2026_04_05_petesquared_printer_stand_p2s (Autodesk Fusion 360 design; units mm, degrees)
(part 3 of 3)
sketch "poop_bin" plane through (203.2508, 0, 0) normal (1, 0, 0) x axis (0, 1, 0)
  line L1 (473.3614, -12.446) -> (87.884, -12.446)
  line L2 (477.012, -33.1964) -> (477.012, -0.508)
  line L3 (87.884, -53.086) -> (481.584, -37.592)
  line L4 (87.884, -12.446) -> (87.884, -53.086)
  line L5 (481.584, -5.08) -> (481.584, -37.592)
  line L6 (92.456, -48.3305) -> (92.456, -12.446)
  line L7 (477.012, -33.1964) -> (92.456, -48.3305)
  line L8 (477.012, -37.7719) -> (477.012, -33.1964)
  line L9 (473.3614, -12.446) -> (473.3614, -33.3401)
  line L10 (138.684, -18.9484) -> (138.684, -12.446)
  line L11 (164.084, -18.9484) -> (138.684, -18.9484)
  line L12 (164.084, -12.446) -> (164.084, -18.9484)
  line L13 (367.284, -18.9484) -> (367.284, -12.446)
  line L14 (392.684, -18.9484) -> (367.284, -18.9484)
  line L15 (392.684, -12.446) -> (392.684, -18.9484)
  line L16 (477.012, -12.446) -> (473.3614, -12.446)
  line L17 (283.4191, -11.9284) -> (284.734, -45.339)
  line L18 (68.8487, -53.8351) -> (87.884, -53.086)
  line L19 (68.8487, -49.0797) -> (68.8487, -53.8351)
  line L20 (87.884, -48.3305) -> (68.8487, -49.0797)
  arc A1 centre (477.012, -5.08) radius 4.572 clockwise from (477.012, -0.508) to (481.584, -5.08)
  point P3 (477.012, -0.508)
  point P7 (477.012, -12.192)
  point P12 (92.456, -12.446)
  point P2 (481.584, -37.592)
  point P9 (481.584, -37.592)
  point P17 (477.012, -37.7719)
  point P18 (473.3614, -33.3401)
  point P20 (138.684, -12.446)
  point P23 (164.084, -12.446)
  point P24 (367.284, -12.446)
  point P27 (392.684, -12.446)
  point P22 (164.084, -18.9484)
  point P25 (367.284, -18.9484)
  point P6 (473.3614, -12.446)
  point P19 (473.3614, -12.446)
  point P16 (477.012, -5.08)
  point P10 (477.012, -0.508)
  point P28 (477.012, -12.446)
  point P29 (284.734, -45.339)
  point P33 (87.884, -48.3305)
  point P13 (92.456, -48.3305)
  point P4 (87.884, -53.086)
  point P5 (87.884, -12.446)
  point P11 (477.012, 0)
  point P15 (481.584, -5.08)
  point P21 (138.684, -18.9484)
  point P32 (68.8487, -49.0797)
  horizontal L1
  vertical L2
  vertical L4
  vertical P3 P7
  parallel L2 L5
  coincident L1 P12
  perpendicular L1 L6
  parallel L3 L7
  tangent L5 A1
  coincident P2 P9
  coincident L3 P17
  parallel L2 L8
  coincident L7 P18
  vertical L9
  coincident L1 P20
  perpendicular L1 L10
  perpendicular L10 L11
  coincident L1 P23
  perpendicular L1 L12
  coincident L1 P24
  perpendicular L1 L13
  perpendicular L13 L14
  coincident L1 P27
  perpendicular L1 L15
  horizontal P22 P25
  equal L11 L14
  coincident P6 P19
  vertical P7 P16
  coincident P3 P10
  coincident L2 P28
  perpendicular L2 L16
  midpoint L3 P29
  perpendicular L3 L17
  coincident L4 P33
  horizontal P13 P33
  collinear L3 L18
  parallel L18 L20
  vertical L19
  dimension "d3058" distance P4 P5 = 40.64
  dimension "d3064" distance P6 P7 = 0.254
  dimension "d3100" distance L3 L7 = 4.572
  dimension "d3101" distance L4 L6 = 4.572 (= "d3100")
  dimension "d3104" distance P10 P11 = 0.508
  dimension "d3105" distance P15 P16 = 4.572
  dimension "d3106" distance P2 P7 = 25.4
  dimension "d3114" distance L2 L9 = 3.6506
  dimension "d3155" distance P21 P22 = 25.4
  dimension "d3156" distance P5 P20 = 50.8
  dimension "d3157" distance P20 P21 = 6.5024
  dimension "d3158" distance P22 P25 = 203.2
  dimension "d3323" distance P2 P4 = 393.7
  dimension "d3325" distance P32 P33 = 19.05
sketch "poop_chute" plane through (0, 0, 0) normal (0, 0, 1) x axis (-1, 0, 0)
  line L1 (214.249, 0) -> (214.249, -477.012)
  line L2 (-214.249, 0) -> (214.249, 0)
  line L3 (-214.249, -477.012) -> (-214.249, 0)
  line L4 (-127, -477.012) -> (-214.249, -477.012)
  line L5 (-127, -417.9654) -> (-127, -477.012)
  line L6 (-113.5296, -404.495) -> (-127, -417.9654)
  line L7 (113.5296, -404.495) -> (-113.5296, -404.495)
  line L8 (127, -417.9654) -> (113.5296, -404.495)
  line L9 (127, -477.012) -> (127, -417.9654)
  line L10 (214.249, -477.012) -> (127, -477.012)
  line L11 (0, -481.584) -> (127, -481.584)
  line L12 (115.4234, -399.923) -> (0, -399.923)
  line L13 (131.572, -477.012) -> (131.572, -416.0716)
  line L14 (150.622, -421.1516) -> (150.622, -471.932)
  line L15 (131.572, -416.0716) -> (145.542, -416.0716)
  line L16 (0, -399.923) -> (0, -481.584)
  line L17 (0, -477.012) -> (0, -481.584)
  line L18 (127, -417.9654) -> (127, -477.012)
  line L19 (113.5296, -404.495) -> (127, -417.9654)
  line L20 (0, -404.495) -> (113.5296, -404.495)
  line L21 (127, -477.012) -> (0, -477.012)
  line L22 (0, -399.923) -> (0, -404.495)
  line L23 (131.572, -416.0716) -> (115.4234, -399.923)
  line L24 (145.542, -477.012) -> (131.572, -477.012)
  line L25 (95.25, -404.495) -> (95.25, -477.012)
  line L26 (95.25, -481.584) -> (95.25, -477.012)
  line L27 (95.25, -399.923) -> (95.25, -404.495)
  line L28 (90.678, -404.495) -> (90.678, -477.012)
  circle C1 centre (141.732, -428.7716) radius 1.905
  circle C2 centre (141.732, -464.312) radius 1.905
  arc A1 centre (145.542, -421.1516) radius 5.08 clockwise from (145.542, -416.0716) to (150.622, -421.1516)
  arc A2 centre (145.542, -471.932) radius 5.08 clockwise from (150.622, -471.932) to (145.542, -477.012)
  arc A3 centre (127, -477.012) radius 4.572 clockwise from (131.572, -477.012) to (127, -481.584)
  circle C3 centre (-171.196, -30.099) radius 1.6002
  circle C4 centre (-171.196, -372.491) radius 1.6002
  circle C5 centre (171.196, -30.099) radius 1.6002
  circle C6 centre (171.196, -372.491) radius 1.6002
  circle C7 centre (-197.1548, -68.326) radius 1.6002
  circle C8 centre (197.1548, -423.926) radius 1.6002
  circle C9 centre (197.1548, -68.326) radius 1.6002
  circle C10 centre (-197.1548, -423.926) radius 1.6002
  circle C11 centre (-152.4, -13.716) radius 1.6002
  circle C12 centre (197.1548, -246.126) radius 1.6002
  circle C13 centre (152.4, -13.716) radius 1.6002
  circle C14 centre (-197.1548, -246.126) radius 1.6002
  circle C15 centre (0, -13.716) radius 1.6002
  point P24 (0, -399.923)
  point P25 (0, 0)
  point P26 (0, -477.012)
  point P27 (127, -417.9654)
  point P29 (0, -404.495)
  point P31 (131.572, -416.0716)
  point P20 (127, -477.012)
  point P32 (127, -477.012)
  point P33 (131.572, -477.012)
  point P34 (141.732, -416.0716)
  point P35 (141.732, -428.7716)
  point P36 (141.732, -464.312)
  point P22 (150.622, -416.0716)
  point P58 (95.25, -477.012)
  point P59 (95.25, -404.495)
  point P60 (95.25, -481.584)
  point P61 (95.25, -399.923)
  point P62 (90.678, -477.012)
  point P63 (90.678, -404.495)
  point P44 (127, -477.012)
  horizontal L11
  horizontal L12
  vertical L13
  perpendicular L12 L14
  perpendicular L13 L15
  vertical P24 P25
  coincident L16 P26
  perpendicular L11 L17
  coincident L9 P27
  midpoint L7 P29
  horizontal L20
  perpendicular L16 L21
  vertical L18
  equal L17 L22
  collinear L8 L19
  coincident L13 P31
  parallel L19 L23
  coincident P20 P32
  horizontal L24
  horizontal P32 P33
  vertical P34 P35
  vertical P34 P36
  coincident L15 P34
  coincident P22 L15
  coincident P22 L14
  tangent L15 A1
  tangent L14 A1
  tangent L14 A2
  tangent L24 A2
  equal A1 A2
  tangent L11 A3
  tangent L13 A3
  coincident L21 P58
  coincident L20 P59
  vertical L25
  coincident L11 P60
  perpendicular L11 L26
  coincident L12 P61
  perpendicular L12 L27
  coincident L21 P62
  coincident L20 P63
  vertical L28
  dimension "d3066" angle L19 L20 = 135
  dimension "d3067" distance L12 L20 = 4.572
  dimension "d3068" distance P20 L13 = 4.572 (= "d3067")
  dimension "d3071" distance L19 L23 = 4.572 (= "d3067")
  dimension "d3080" distance P22 P31 = 19.05
  dimension "d3081" diameter C1 = 3.81 (= "hole_screw_3dprint")
  dimension "d3082" distance P34 P35 = 12.7 (= "hole_screw_brace_offset / 2")
  dimension "d3083" diameter C2 = 3.81 (= "hole_screw_3dprint")
  dimension "d3084" distance L24 P36 = 12.7 (= "hole_screw_brace_offset / 2")
  dimension "d3085" radius A1 = 5.08
  dimension "d3086" distance P31 P34 = 10.16
  dimension "d3662" distance P44 P58 = 31.75
  dimension "d3663" distance P60 P62 = 4.572 (= "d3067")
extrude "Extrude1" new body sketch "poop_chute" profile of L7 L11 L12 L17 L20 L21 L22 L25 L26 L27 L28 along normal blind 203.2 bodies "poop_chute"
draft "Draft1" Angle1 45 Angle2 0
extrude "Extrude2" add sketch "poop_chute" profile of L7 L8 L9 L11 L12 L13 L14 L15 L18 L19 L20 L21 L23 L24 C1 C2 A1 A2 A3 L25 L26 L27 along normal blind 6.35
chamfer "Chamfer1" distance 3.81
mirror "Mirror1" mirrorStitchTolerance 0.1016
fillet "Fillet1" radius 1.524
sketch "base_bracket_feet" plane through (0, 0, -83.312) normal (0, 0, -1) x axis (1, 0, 0)
  line L1 (-103.0086, -418.3296) -> (-81.28, -483.616)
  line L2 (-138.9296, -382.4086) -> (-103.0086, -418.3296)
  line L3 (-204.216, -360.68) -> (-138.9296, -382.4086)
  line L4 (-220.98, -360.68) -> (-204.216, -360.68)
  line L5 (-220.98, -500.38) -> (-220.98, -360.68)
  line L6 (-81.28, -500.38) -> (-220.98, -500.38)
  line L7 (-81.28, -483.616) -> (-81.28, -500.38)
  line L8 (-220.98, -500.38) -> (-144.78, -500.38)
  line L9 (-220.98, -424.18) -> (-220.98, -500.38)
  line L10 (-144.78, -473.4392) -> (-144.78, -500.38)
  line L11 (-194.0392, -424.18) -> (-220.98, -424.18)
  line L12 (-194.0392, -424.18) -> (-144.78, -473.4392)
  line L13 (-220.98, -102.362) -> (-220.98, -26.162)
  line L14 (-194.0392, -102.362) -> (-220.98, -102.362)
  line L15 (-144.78, -26.162) -> (-144.78, -53.1028)
  line L16 (-220.98, -26.162) -> (-144.78, -26.162)
  line L17 (-144.78, -53.1028) -> (-194.0392, -102.362)
  line L18 (-182.88, -26.162) -> (-182.88, -64.262)
  line L19 (-220.98, -64.262) -> (-182.88, -64.262)
  line L20 (-220.98, -462.28) -> (-182.88, -462.28)
  line L21 (-182.88, -500.38) -> (-182.88, -462.28)
  line L22 (0, -20) -> (0, -2.5)
  circle C1 centre (-152.4, -431.8) radius 8.128
  circle C2 centre (-152.4, -76.2) radius 5.207
  circle C3 centre (-182.88, -462.28) radius 6.096
  circle C4 centre (-182.88, -64.262) radius 6.096
  circle C5 centre (182.88, -462.28) radius 6.096
  circle C6 centre (182.88, -64.262) radius 6.096
  point P13 (-220.98, -424.18)
  point P15 (-220.98, -424.18)
  point P10 (-220.98, -500.38)
  point P17 (-220.98, -500.38)
  point P19 (-220.98, -102.362)
  point P26 (-182.88, -64.262)
  point P27 (-182.88, -64.262)
  point P28 (-182.88, -26.162)
  point P29 (-182.88, -64.262)
  point P30 (-220.98, -64.262)
  point P32 (-220.98, -462.28)
  point P25 (-182.88, -462.28)
  point P33 (-182.88, -462.28)
  point P34 (-182.88, -500.38)
  point P31 (-182.88, -462.28)
  point P12 (-144.78, -500.38)
  point P18 (-220.98, -26.162)
  point P23 (-216.408, -30.734)
  horizontal L8
  perpendicular L8 L9
  equal L8 L9
  perpendicular L8 L10
  perpendicular L9 L11
  equal L10 L11
  coincident P13 P15
  coincident P10 P17
  vertical L13
  perpendicular L13 L14
  horizontal L16
  vertical P13 P19
  equal L11 L14
  equal L9 L13
  vertical L15
  equal L14 L15
  coincident P26 P27
  coincident L16 P28
  perpendicular L16 L18
  coincident P26 P29
  coincident L13 P30
  perpendicular L13 L19
  equal L18 L19
  coincident L9 P32
  coincident P25 P33
  coincident L8 P34
  horizontal L20
  vertical L21
  equal L20 L21
  equal L19 L20
  coincident P25 P31
  symmetric C3 L22 C5
  symmetric C4 L22 C6
  dimension "d3508" distance P10 P12 = 76.2
  dimension "d3523" distance P18 P23 = 4.572 (= "dado_material_depth")
  dimension "d3587" diameter C3 = 12.192 (= "hole_threaded_inserts")
  dimension "d3588" distance P17 P25 = 38.1
  dimension "d3590" distance L12 P25 = 19.05
  dimension "d3592" angle L14 L17 = 135
  dimension "d3594" diameter C4 = 12.192 (= "hole_threaded_inserts")
extrude "Extrude34" new body sketch "base_bracket_feet" profile of L5 L6 L8 L9 L10 L11 L12 L13 L14 L15 L16 C3 L17 C4 along normal blind 12.192 (= "material_thickness") bodies "base_bracket_foot_back_left", "base_bracket_foot_front_left"
mirror "Mirror8" mirrorStitchTolerance 0.1016 bodies "base_bracket_foot_back_right", "base_bracket_foot_front_right"
fillet "Fillet3" radius 5.969
extrude "Extrude6" new body sketch "poop_bin" profile of L1 L10 L11 L12 L13 L14 L15 blind -6.35 from offset -18.796 (= "-material_thickness - 0.26 in")
extrude "Extrude7" sketch "poop_bin" profile of L1 L2 L3 L4 L6 L7 L8 L9 L10 L11 L12 L13 L14 L15 L16 blind -4.572 (= "-wall_thickness_3d_printed")
extrude "Extrude8" sketch "poop_bin" profile of L1 L2 L3 L4 L6 L7 L8 L9 L16 to an object
extrude "Extrude18" sketch "poop_bin" profile of L4 L18 L19 L20 blind 50.8
extrude "Extrude9" add sketch "poop_bin" profile of L2 L3 L5 A1 L8 to an object from offset -62.23
work_plane "WorkPlane2" RotateAngle 90
split "Split2"
mirror "Mirror7" mirrorStitchTolerance 0.1016
step "SurfaceRuled2" ruledDistance 5.08 ruledAngle 0
rectangular_pattern "R-Pattern2" uSpaceDistance -152.4 vSpaceDistance 0
split_face "SplitFace24"
step "SurfaceRuled3" ruledDistance 5.08 ruledAngle 0
rectangular_pattern "R-Pattern3" uSpaceDistance 170.18 vSpaceDistance 0
split_face "SplitFace25"
sketch "poop_bin_cutters_a" plane through (0, 0, 0) normal (1, 0, 0) x axis (0, 1, 0)
  line L1 (481.584, -5.08) -> (481.584, -37.592)
  line L2 (477.012, -12.446) -> (477.012, -0.508)
  line L3 (473.3614, -12.446) -> (477.012, -12.446)
  line L4 (473.3614, -33.3401) -> (473.3614, -12.446)
  line L5 (454.6026, -34.0783) -> (473.3614, -33.3401)
  line L6 (481.584, -37.592) -> (473.3614, -33.3401)
  line L7 (481.584, -37.592) -> (454.7824, -38.6468)
  line L8 (114.6856, -52.0312) -> (68.8487, -53.8351)
  line L9 (87.884, -53.086) -> (92.456, -48.3305)
  line L10 (87.884, -48.3305) -> (87.884, -53.086)
  arc A1 centre (477.012, -5.08) radius 4.572 clockwise from (477.012, -0.508) to (481.584, -5.08)
  point P8 (473.3614, -33.3401)
  point P9 (473.3614, -33.3401)
  point P11 (481.584, -37.592)
  point P12 (481.584, -37.592)
  point P20 (87.884, -53.086)
  point P10 (92.456, -48.3305)
  point P23 (92.456, -48.3305)
  point P13 (87.884, -48.3305)
  point P24 (87.884, -48.3305)
  coincident P8 P9
  coincident P11 P12
  coincident P20 L8
  coincident P10 P23
  vertical P13 P20
  coincident P13 P24
split_face "SplitFace26"
split_face "SplitFace27"
sketch "poop_bin_cutters_b" plane through (0, 282.5121, 11.1182) normal (0, -0.9992, -0.0393) x axis (1, 0, 0)
  line L1 (152.4, -56.5009) -> (152.4, -51.9289)
  line L2 (178.1048, -56.5009) -> (152.4, -56.5009)
  line L3 (178.1048, -23.5825) -> (178.1048, -56.5009)
  line L4 (173.5328, -23.5825) -> (178.1048, -23.5825)
  line L5 (173.5328, -51.9289) -> (173.5328, -23.5825)
  line L6 (152.4, -51.9289) -> (173.5328, -51.9289)
  line L7 (178.1048, -56.5009) -> (173.5328, -51.9289)
  line L8 (-178.1048, -56.5009) -> (-173.5328, -51.9289)
  point P7 (173.5328, -51.9289)
  point P8 (173.5328, -51.9289)
  point P4 (178.1048, -56.5009)
  point P9 (178.1048, -56.5009)
  point P10 (-173.5328, -51.9289)
  point P12 (-173.5328, -51.9289)
  point P11 (-178.1048, -56.5009)
  point P13 (-178.1048, -56.5009)
  coincident P7 P8
  coincident P4 P9
  coincident P10 P12
  coincident P11 P13
split_face "SplitFace28"
split_face "SplitFace29"
draft "Draft25" Angle1 35 Angle2 0
draft "Draft26" Angle1 -35 Angle2 0
draft "Draft27" Angle1 -35 Angle2 0
draft "Draft28" Angle1 35 Angle2 0
fillet "Fillet6" radius 12.7
sketch "poop_bin_bracket" plane through (191.0588, 0, 0) normal (-1, 0, 0) x axis (0, -1, 0)
  line L1 (-15.24, -53.848) -> (-471.043, -53.848)
  line L2 (-15.24, -7.62) -> (-15.24, -53.848)
  line L3 (-477.012, -7.62) -> (-15.24, -7.62)
  line L4 (-477.012, -47.879) -> (-477.012, -7.62)
  line L5 (-138.684, -18.9484) -> (-163.83, -18.9484)
  line L6 (-138.684, -12.192) -> (-138.684, -18.9484)
  line L7 (-165.1, -22.7584) -> (-165.1, -19.0754)
  line L8 (-471.043, -12.192) -> (-19.812, -12.192)
  line L9 (-132.334, -29.1084) -> (-387.35, -29.1084)
  line L10 (-125.984, -12.192) -> (-125.984, -22.7584)
  line L11 (-367.284, -18.9484) -> (-367.284, -12.192)
  line L12 (-392.43, -18.9484) -> (-367.284, -18.9484)
  line L13 (-393.7, -22.7584) -> (-393.7, -18.8214)
  line L14 (-259.842, -12.192) -> (-259.842, -29.1084)
  line L15 (-125.984, -12.192) -> (-138.684, -12.192)
  line L16 (-393.7, -12.192) -> (-393.7, -18.8214)
  line L17 (-138.684, -12.192) -> (-393.7, -12.192)
  line L18 (-354.584, -22.7584) -> (-354.584, -12.192)
  line L19 (-387.35, -22.7584) -> (-388.4276, -23.836)
  line L20 (-183.119, -29.1084) -> (-164.7793, -18.52)
  line L21 (-412.159, -29.1084) -> (-387.35, -29.1084)
  line L22 (-393.3793, -18.266) -> (-412.159, -29.1084)
  line L23 (-409.3832, -12.192) -> (-409.3832, -28.0924)
  line L24 (-409.3832, -12.192) -> (-393.7, -12.192)
  arc A1 centre (-471.043, -47.879) radius 5.969 clockwise from (-471.043, -53.848) to (-477.012, -47.879)
  circle C1 centre (-80.264, -36.1315) radius 1.6002
  circle C2 centre (-240.7285, -36.1315) radius 1.6002
  circle C3 centre (-400.812, -36.1315) radius 1.6002
  arc A2 centre (-164.4587, -19.0754) radius 0.6413 clockwise from (-165.1, -19.0754) to (-163.83, -18.9484)
  arc A3 centre (-132.334, -22.7584) radius 6.35 clockwise from (-125.984, -22.7584) to (-132.334, -29.1084)
  arc A4 centre (-393.0587, -18.8214) radius 0.6413 clockwise from (-393.7, -18.8214) to (-392.43, -18.9484)
  arc A5 centre (-387.35, -22.7584) radius 6.35 clockwise from (-387.35, -29.1084) to (-393.7, -22.7584)
  circle C4 centre (-259.842, -22.7584) radius 1.905
  circle C5 centre (-132.334, -22.7584) radius 1.905
  circle C6 centre (-388.4276, -23.836) radius 1.905
  arc A6 centre (-360.934, -22.7584) radius 6.35 clockwise from (-354.584, -22.7584) to (-360.934, -29.1084)
  arc A7 centre (-158.75, -22.7584) radius 6.35 clockwise from (-158.75, -29.1084) to (-165.1, -22.7584)
  circle C7 centre (-132.334, -22.7584) radius 3.556
  circle C8 centre (-259.842, -22.7584) radius 3.556
  circle C9 centre (-388.4276, -23.836) radius 3.556
  circle C10 centre (-132.334, -22.7584) radius 1.6002
  circle C11 centre (-259.842, -22.7584) radius 1.6002
  circle C12 centre (-388.4276, -23.836) radius 1.6002
  arc A8 centre (-179.3273, -28.0924) radius 1.016 clockwise from (-179.3273, -29.1084) to (-179.8353, -27.2125)
  arc A9 centre (-408.3672, -28.0924) radius 1.016 clockwise from (-408.3672, -29.1084) to (-408.8752, -27.2125)
  point P11 (-138.684, -18.9484)
  point P16 (-138.684, -18.9484)
  point P12 (-138.684, -12.192)
  point P22 (-125.984, -12.192)
  point P24 (-367.284, -18.9484)
  point P26 (-367.284, -18.9484)
  point P23 (-367.284, -12.192)
  point P35 (-259.842, -29.1084)
  point P36 (-259.842, -12.192)
  point P38 (-393.7, -12.192)
  point P21 (-132.334, -22.7584)
  point P37 (-132.334, -22.7584)
  point P34 (-259.842, -22.7584)
  point P40 (-354.584, -12.192)
  point P42 (-360.934, -29.1084)
  point P45 (-158.75, -29.1084)
  point P39 (-388.4276, -23.836)
  point P49 (-388.4276, -23.836)
  point P50 (-388.4276, -23.836)
  point P33 (-387.35, -22.7584)
  point P51 (-387.35, -22.7584)
  point P55 (-164.7793, -18.52)
  point P56 (-183.119, -29.1084)
  point P58 (-179.3273, -29.1084)
  point P57 (-179.8353, -27.2125)
  point P61 (-393.3793, -18.266)
  point P63 (-408.3672, -29.1084)
  point P62 (-408.8752, -27.2125)
  point P65 (-409.3832, -28.0924)
  point P66 (-409.3832, -12.192)
  point P13 (-165.1, -19.0754)
  point P27 (-163.83, -18.9484)
  point P15 (-164.084, -18.9484)
  point P25 (-392.43, -18.9484)
  point P30 (-392.684, -18.9484)
  point P28 (-393.7, -18.8214)
  parallel L3 L5
  perpendicular L3 L6
  vertical L7
  tangent A2 L7
  coincident P11 P16
  coincident P12 L8
  horizontal L9
  tangent L9 A3
  coincident L8 P22
  perpendicular L8 L10
  tangent A3 L10
  vertical L11
  perpendicular L11 L12
  coincident P24 P26
  coincident L8 P23
  vertical L13
  tangent A4 L13
  equal A2 A4
  tangent L13 A5
  tangent L9 A5
  equal A3 A5
  midpoint L9 P35
  coincident L8 P36
  perpendicular L8 L14
  coincident L8 P38
  tangent A4 L16
  coincident P21 P37
  coincident P34 L14
  horizontal P34 P37
  coincident L17 P40
  vertical L18
  tangent L9 A6
  coincident L9 P42
  tangent L18 A6
  equal A3 A6
  tangent L9 A7
  coincident L9 P45
  tangent L7 A7
  equal A5 A7
  concentric A3 C7
  concentric C4 C8
  coincident P39 P49
  coincident P39 P50
  coincident P33 P51
  concentric C7 C10
  concentric C4 C11
  concentric C9 C12
  coincident A2 P55
  coincident L9 P56
  tangent A2 L20
  tangent L9 A8
  coincident L9 P58
  coincident L20 P57
  tangent L20 A8
  tangent A5 L21
  coincident A4 P61
  tangent A4 L22
  tangent L21 A9
  coincident L21 P63
  coincident L22 P62
  tangent L22 A9
  coincident A9 P65
  coincident L8 P66
  perpendicular L8 L23
  tangent A9 L23
  equal A8 A9
  dimension "d3341" distance P13 P27 = 1.27
  dimension "d3342" distance P13 P27 = 0.127
  dimension "d3344" radius A3 = 6.35
  dimension "d3345" distance P12 P22 = 12.7
  dimension "d3346" distance P15 P27 = 0.254
  dimension "d3347" distance P25 P30 = 0.254
  dimension "d3348" distance P25 P28 = 1.27 (= "d3341")
  dimension "d3349" diameter C4 = 3.81 (= "hole_screw_3dprint")
  dimension "d3350" diameter C5 = 3.81 (= "hole_screw_3dprint")
  dimension "d3351" diameter C6 = 3.81 (= "hole_screw_3dprint")
  dimension "d3354" distance P23 P40 = 12.7
  dimension "d3355" distance L5 L9 = 10.16
  dimension "d3397" diameter C7 = 7.112 (= "hole_screwhead")
  dimension "d3398" diameter C8 = 7.112 (= "hole_screwhead")
  dimension "d3399" diameter C9 = 7.112 (= "hole_screwhead")
  dimension "d3400" angle L9 L19 = 45
  dimension "d3402" = 1.27
  dimension "d3642" diameter C10 = 3.2004 (= "hole_screw")
  dimension "d3643" diameter C11 = 3.2004 (= "hole_screw")
  dimension "d3644" diameter C12 = 3.2004 (= "hole_screw")
  dimension "d3659" angle L9 L20 = 30
  dimension "d3660" radius A8 = 1.016
  dimension "d3661" angle L21 L22 = 30 (= "d3659")
extrude "Extrude19" new body sketch "poop_bin_bracket" profile of L5 L6 A2 L7 L9 A3 L10 L11 L12 A4 L13 A5 C4 C5 L15 L16 L17 C6 L18 A6 A7 C7 C8 C9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 along normal blind 6.35 bodies "poop_bin_bracket_right"
extrude "Extrude20" sketch "poop_bin_bracket" profile of L5 L6 A2 L7 L9 A3 L10 L11 L12 A4 L13 A5 C5 L15 L16 L17 C6 L18 A6 A7 C7 C9 L20 A8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 blind 6.35
extrude "Extrude21" sketch "poop_bin_bracket" profile of C5 C6 C7 C9 to an object
chamfer "Chamfer3" distance 1.651
offset_faces "OffsetFaces3" distance -0.1016
fillet "Fillet7" radius 1.016 1.524
fillet "Fillet9" radius 1.27
mirror "Mirror8" mirrorStitchTolerance 0.1016 bodies "poop_bin_bracket_left"
sketch "Sketch12" plane through (0, 0, 0) normal (0, 1, 0) x axis (1, 0, 0)
  dimension "d3664" = 50.8
  dimension "d3665" = 0 (= "Text1-Text")
sketch "Sketch1" plane through (0, 0, 0) normal (0, 0, 1) x axis (1, 0, 0)
  line L1 (1981.2, 533.4) -> (762, 533.4)
  line L2 (1981.2, -1905) -> (1981.2, 533.4)
  line L3 (762, -1905) -> (1981.2, -1905)
  line L4 (762, 533.4) -> (762, -1905)
  point P2 (762, 533.4)
  point P3 (1981.2, 533.4)
  point P5 (762, -1905)
  horizontal L1
  vertical L2
  horizontal L3
  vertical L4
  dimension "d3379" distance P2 P3 = 1219.2 (= "4'-0")
  dimension "d3380" distance P2 P5 = 2438.4 (= "8'-0")
sketch "printer_shelf_holes_poop_chute" plane through (0, 0, 0) normal (0, 0, 1) x axis (1, 0, 0)
  circle C1 centre (-141.732, 428.7716) radius 1.6002
  circle C2 centre (-141.732, 464.312) radius 1.6002
  circle C3 centre (141.732, 464.312) radius 1.6002
  circle C4 centre (141.732, 428.7716) radius 1.6002
  circle C5 centre (141.732, 464.312) radius 1.905
  circle C6 centre (141.732, 428.7716) radius 1.905
  point P2 (-141.732, 428.7716)
  point P3 (-141.732, 428.7716)
  point P4 (-141.732, 464.312)
  point P5 (-141.732, 464.312)
  point P7 (141.732, 428.7716)
  point P9 (141.732, 428.7716)
  point P6 (141.732, 464.312)
  point P8 (141.732, 464.312)
  coincident P2 P3
  coincident P4 P5
  coincident P7 P9
  coincident P6 P8
  dimension "d3383" diameter C1 = 3.2004 (= "hole_screw")
  dimension "d3384" diameter C2 = 3.2004 (= "hole_screw")
  dimension "d3385" diameter C4 = 3.2004 (= "hole_screw")
  dimension "d3386" diameter C3 = 3.2004 (= "hole_screw")
extrude "Extrude27" cut sketch "printer_shelf_holes_poop_chute" profile of C1 C2 C3 C4 to an object
extrude "Extrude28" sketch "poop_bin_bracket" profile of C10 C11 C12 to an object
copy_paste_bodies "CopyPasteBodies9"
move "Move18"
copy_paste_bodies "CopyPasteBodies8"
move "Move17"
sketch "ams_back" plane through (0, 508, 0) normal (0, 1, 0) x axis (1, 0, 0)
  line L1 (161.925, -852.297) -> (220.98, -852.297)
  line L2 (161.925, -580.263) -> (161.925, -852.297)
  line L3 (220.98, -580.263) -> (161.925, -580.263)
  line L4 (220.98, -852.297) -> (220.98, -580.263)
  circle C1 centre (207.9625, -837.6285) radius 1.6002
  circle C2 centre (174.9425, -837.6285) radius 1.6002
  circle C3 centre (207.9625, -594.9315) radius 1.6002
  circle C4 centre (174.9425, -594.9315) radius 1.6002
  point P2 (220.98, -852.297)
  point P6 (220.98, -852.297)
  point P4 (161.925, -580.263)
  point P9 (161.925, -580.263)
  horizontal L1
  vertical L2
  horizontal L3
  vertical L4
  coincident P2 P6
  coincident P4 P9
extrude "Extrude29" new body sketch "ams_back" no distance stored bodies "ams_back_left"
mirror "Mirror4" mirrorStitchTolerance 0.1016 bodies "ams_back_right"
copy_paste_bodies "CutPasteBodies"
combine "Combine3"
combine "Combine4"
offset_faces "OffsetFaces1" distance -0.762
offset_faces "OffsetFaces3" distance -0.508
offset_faces "OffsetFaces3" distance -0.508
extrude "Extrude36" cut sketch "base_bracket_feet" profile of C3 C4 C5 C6 to an object
extrude "Extrude32" sketch "runner" profile of C7 C8 C9 blind 6.096 (= "material_thickness / 2") Side2Offset -6.096 (= "-material_thickness / 2")
sketch "Sketch1" plane through (0, 508, 0) normal (0, 1, 0) x axis (1, 0, 0)
  line L1 (160.02, -467.36) -> (-160.02, -467.36)
  line L2 (160.02, -422.91) -> (160.02, -467.36)
  line L3 (-160.02, -422.91) -> (160.02, -422.91)
  line L4 (-160.02, -467.36) -> (-160.02, -422.91)
  line L5 (0, -422.91) -> (0, -467.36)
  line L6 (161.925, -467.36) -> (-161.925, -467.36)
  circle C1 centre (0, -445.135) radius 1.6002
  circle C2 centre (0, -445.135) radius 3.556
  circle C3 centre (-152.4, -445.135) radius 1.6002
  circle C4 centre (-152.4, -445.135) radius 3.556
  circle C5 centre (-101.6, -445.135) radius 1.6002
  circle C6 centre (-101.6, -445.135) radius 3.556
  circle C7 centre (-50.8, -445.135) radius 1.6002
  circle C8 centre (-50.8, -445.135) radius 3.556
  circle C9 centre (50.8, -445.135) radius 1.6002
  circle C10 centre (50.8, -445.135) radius 3.556
  circle C11 centre (101.6, -445.135) radius 1.6002
  circle C12 centre (101.6, -445.135) radius 3.556
  circle C13 centre (152.4, -445.135) radius 1.6002
  circle C14 centre (152.4, -445.135) radius 3.556
  point P6 (0, -467.36)
  point P7 (0, -422.91)
  point P1 (0, 0)
  point P10 (0, -445.135)
  point P2 (-160.02, -467.36)
  point P3 (160.02, -467.36)
  point P5 (-160.02, -422.91)
  horizontal L1
  vertical L2
  horizontal L3
  vertical L4
  midpoint L1 P6
  midpoint L3 P7
  vertical P1 P7
  coincident P6 L6
  midpoint L5 P10
  concentric C1 C2
  dimension "d3620" distance P2 P3 = 320.04
  dimension "d3621" distance P2 P5 = 44.45
  dimension "d3622" diameter C1 = 3.2004 (= "hole_screw")
  dimension "d3623" diameter C2 = 7.112 (= "hole_screwhead")
  dimension "d3626" R-Pattern1-uDistance = 152.4
  dimension "d3627" R-Pattern1-vDistance = 0
extrude "Extrude1" new body sketch "Sketch1" profile of L1 L2 L3 L4 C1 C2 C3 C4 C5 C6 C7 C8 C9 C10 C11 C12 C13 C14 no distance stored
extrude "Extrude2" sketch "Sketch1" profile of C1 C2 C3 C4 C5 C6 C7 C8 C9 C10 C11 C12 C13 C14 blind 3.302 (= "dado_screwhead_depth")
fillet "Fillet1" radius 12.7
draft "Draft1" Angle1 -45 Angle2 0
copy_paste_bodies "CopyPasteBodies1"
move "Move1"
mirror "Mirror6" mirrorStitchTolerance 0.1016 bodies "ams_top_front"
fillet "Fillet4" radius 2.54
offset_faces "OffsetFaces2" distance -0.508
copy_paste_bodies "CopyPasteBodies86"
move "Move1101"
move "Move1102"
move "Move1103"
move "Move1104"
move "Move1105"
move "Move1106"
move "Move1107"
move "Move1108"
move "Move1109"
move "Move1110"
move "Move1111"
move "Move1112"
move "Move1113"
move "Move1114"
move "Move1115"
move "Move1116"
move "Move1117"
move "Move1118"
move "Move1119"
move "Move1120"
move "Move1121"
move "Move1122"
move "Move1123"
move "Move1124"
move "Move1125"
move "Move1126"
move "Move1127"
move "Move1128"
move "Move1129"
move "Move1130"
move "Move1131"
move "Move1132"
move "Move1133"
move "Move1134"
move "Move1135"
move "Move1136"
move "Move1137"
move "Move1138"
move "Move1139"
move "Move1140"
move "Move1141"
move "Move1142"
move "Move1143"
move "Move1144"
move "Move1145"
move "Move1146"
move "Move1147"
move "Move1148"
move "Move1149"
move "Move1150"
move "Move1151"
move "Move1152"
move "Move1153"
move "Move1154"
move "Move1155"
move "Move1156"
move "Move1157"
move "Move1158"
move "Move1159"
move "Move1160"
move "Move1161"
move "Move1162"
move "Move1163"
move "Move1164"
move "Move1165"
move "Move1166"
move "Move1167"
move "Move1168"
move "Move1169"
move "Move1170"
move "Move1171"
move "Move1172"
move "Move1173"
move "Move1174"
move "Move1175"
move "Move1176"
move "Move1177"
move "Move1178"
move "Move1179"
move "Move1180"
move "Move1181"
move "Move1182"
move "Move1183"
move "Move1184"
move "Move1185"
move "Move1186"
move "Move1187"
move "Move1188"
move "Move1189"
move "Move1190"
move "Move1191"
move "Move1192"
move "Move1193"
move "Move1194"
move "Move1195"
move "Move1196"
move "Move1197"
move "Move1198"
move "Move1199"
move "Move1200"
move "Move1201"
move "Move1202"
move "Move1203"
move "Move1204"
move "Move1205"
move "Move1206"
move "Move1207"
move "Move1208"
move "Move1209"
move "Move1210"
move "Move1211"
move "Move1212"
move "Move1213"
move "Move1214"
move "Move1215"
move "Move1216"
move "Move1217"
move "Move1218"
move "Move1219"
move "Move1220"
move "Move1221"
move "Move1222"
move "Move1223"
move "Move1224"
move "Move1225"
move "Move1226"
move "Move1227"
move "Move1228"
move "Move1229"
move "Move1230"
move "Move1231"
move "Move1232"
move "Move1233"
move "Move1234"
move "Move1235"
move "Move1236"
move "Move1237"
move "Move1238"
move "Move1239"
move "Move1240"
move "Move1241"
move "Move1242"
move "Move1243"
move "Move1244"
move "Move1245"
move "Move1246"
move "Move1247"
move "Move1248"
move "Move1249"
move "Move1250"
move "Move1251"
move "Move1252"
move "Move1253"
move "Move1254"
move "Move1255"
move "Move1256"
move "Move1257"
move "Move1258"
move "Move1259"
move "Move1260"
move "Move1261"
move "Move1262"
move "Move1263"
move "Move1264"
move "Move1265"
move "Move1266"
move "Move1267"
move "Move1268"
move "Move1269"
move "Move1270"
move "Move1271"
move "Move1272"
move "Move1273"
move "Move1274"
move "Move1275"
move "Move1276"
move "Move1277"
move "Move1278"
move "Move1279"
move "Move1280"
move "Move1281"
move "Move1282"
move "Move1283"
move "Move1284"
move "Move1285"
move "Move1286"
move "Move1287"
move "Move1288"
move "Move1289"
move "Move1290"
move "Move1291"
move "Move1292"
move "Move1293"
move "Move1294"
move "Move1295"
move "Move1296"
move "Move1297"
move "Move1298"
move "Move1299"
move "Move1300"
move "Move1301"
move "Move1302"
move "Move1303"
move "Move1304"
move "Move1305"
move "Move1306"
move "Move1307"
move "Move1308"
move "Move1309"
move "Move1310"
move "Move1311"
move "Move1312"
move "Move1313"
move "Move1314"
move "Move1315"
move "Move1316"
move "Move1317"
move "Move1318"
align "Align8"
align "Align9"
move "Move1319"
move "Move1320"
align "Align10"
align "Align11"
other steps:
base_feature "Base Feature4" bodies "ams_shelf_support_right", "ams_shelf_support_left", "ams_shelf_front", "ams_shelf_top"
base_feature "Base Feature1"
fillet "Fillet1" radius 5.969
base_feature "Base Feature86" bodies "printer_top_bracket_left", "base_side_right", "ams_back_support_bottom_a", "cap_bottom", "printer_back_support_top_a", "printer_back_support_bottom_b", "base_bracket_front_left", "printer_brace_right"
fillet "Fillet3" radius 5.969
base_feature "Base Feature2" bodies "printer_top_bracket_right", "printer_top_front", "printer_top_bracket_left", "base_bracket_right_top", "base_bracket_top", "base_bracket_left_top"
fillet "Fillet2" radius 5.969
fillet "Fillet2" radius 5.969
base_feature "Base Feature9" bodies "printer_shelf_top", "printer_shelf_front", "printer_bottom_front", "printer_shelf_support_right", "printer_shelf_support_left", "printer_bottom_bracket_left", "printer_bottom_bracket_right", "printer_back_support_bottom_b"
base_feature "Base Feature8" bodies "printer_back_support_top_a", "printer_back_support_top_b", "printer_top_bracket_left", "printer_top_bracket_right", "ams_back_support_top_a", "ams_back_support_top_b", "ams_top_bracket_left", "ams_top_bracket_right"
extrude "Extrude31" cut sketch "base_bracket_feet" profile of C3 C4 C5 C6 to an object
fillet "Fillet3" radius 2.54
offset_faces "OffsetFaces2" distance -0.762
extrude "Extrude67" cut sketch "base_bracket_feet" profile of C3 C4 C5 C6 to an object
create_component "CreateComponent1"
create_component "CreateComponent2"
create_component "CreateComponent1"
create_component "CreateComponent3"
create_component "CreateComponent1"
create_component "CreateComponent9"
create_component "CreateComponent18"
create_component "CreateComponent2"
create_component "CreateComponent3"
create_component "CreateComponent21"
reparent_decal "ReparentDecal18"
remove_body "RemoveBody18"
reparent_decal "ReparentDecal19"
remove_body "RemoveBody19"
reparent_decal "ReparentDecal20"
remove_body "RemoveBody20"
reparent_decal "ReparentDecal21"
remove_body "RemoveBody21"
create_component "CreateComponent22"
named bodies: "printer_size", "printer_bottom_front", "printer_bottom_bracket_left", "printer_bottom_bracket_right", "printer_side_right", "printer_top_front", "printer_top_bracket_left", "printer_top_bracket_right", "printer_side_left", "printer_shelf_top", "printer_shelf_front", "printer_shelf_support_left", "printer_shelf_support_right", "base_bracket_right_top", "base_bracket_top", "base_bracket_left_top", "base_side_right", "base_back", "base_side_left", "base_bracket_front_right", "base_bracket_front_left", "ams_side_left", "printer_shelf_runner_right", "ams_side_right", "printer_brace_right", "cap_bottom", "cap_side_right", "cap_back", "cap_side_left", "printer_back_support_top_a", "printer_brace_left", "printer_back_support_top_b", "printer_back_left", "printer_back_right", "printer_back_support_bottom_a", "printer_back_support_bottom_b", "printer_top_light_bracket_optional", "poop_chute", "runner_right", "poop_bin_front_right", "poop_bin_back_right", "poop_bin_front_left", "poop_bin_back_left", "poop_bin_bracket_right", "poop_bin_bracket_left", "printer_back_support_bottom_a (1)", "ams_back_support_top_a", "ams_back_support_top_b", "ams_top_bracket_left", "ams_top_bracket_right", "ams_back_left", "ams_back_right", "ams_shelf_top", "ams_shelf_front", "ams_bottom_front", "ams_shelf_support_right", "ams_shelf_support_left", "ams_bottom_bracket_left", "ams_bottom_bracket_right", "ams_back_support_bottom_b"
